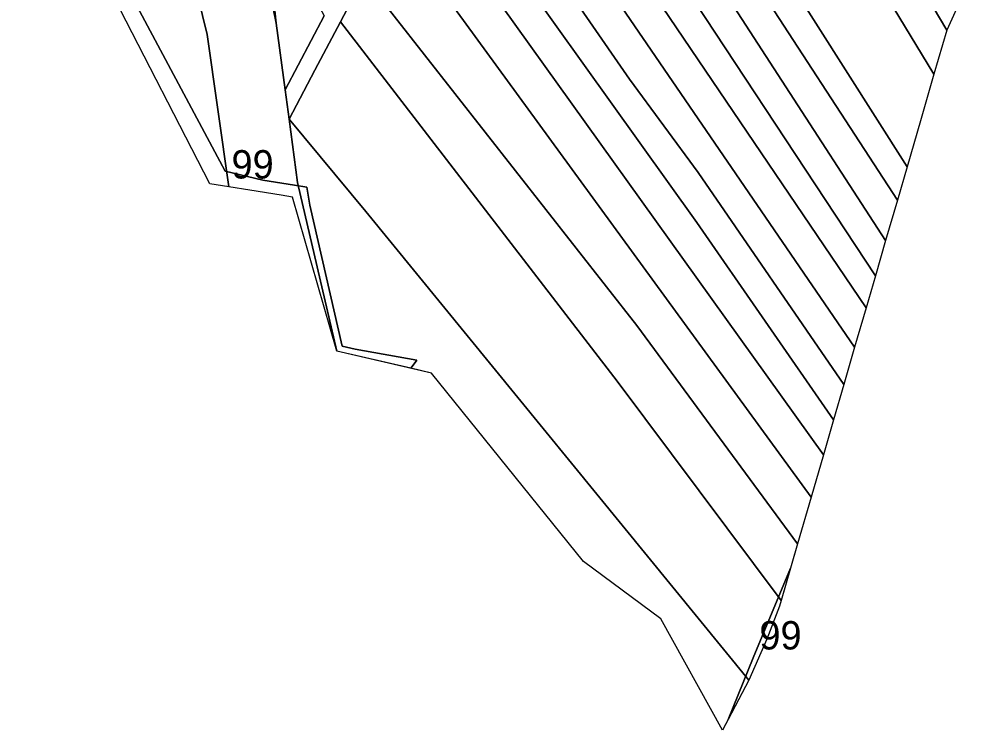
# Model space of a CAD drawing. Extents: x -535894 to -532834, y -1165802 to -1163645.
# Drawn here: x -534290.4 to -534123.9, y -1165556.9 to -1165431.5 of the extents above; entities that cross this region are included whole.
import ezdxf

# ---------------------------------------------------------------- set-up
doc = ezdxf.new("R2010")
doc.units = 0
for name, color, linetype in [('95610013', 7, 'Continuous'), ('95640013', 7, 'Continuous'), ('95660013', 7, 'Continuous')]:
    doc.layers.add(name, color=color, linetype=linetype)

msp = doc.modelspace()

# ---------------------------------------------------------------- linework, layer by layer
at = {"layer": '95610013'}
for points in [[(-534171.44, -1165359.48), (-534166.84, -1165354.83), (-534148.33, -1165384.9), (-534123.86, -1165427.13), (-534126.75, -1165433.55), (-534152.03, -1165390.89)], [(-534176.44, -1165364.53), (-534171.44, -1165359.48), (-534152.03, -1165390.89), (-534126.75, -1165433.55), (-534129.01, -1165441.31), (-534156.72, -1165395.63)], [(-534181.53, -1165369.66), (-534176.44, -1165364.53), (-534156.72, -1165395.63), (-534129.01, -1165441.31), (-534131.39, -1165449.51), (-534133.74, -1165457.61), (-534186.43, -1165374.61)], [(-534190.57, -1165378.79), (-534186.43, -1165374.61), (-534133.74, -1165457.61), (-534135.45, -1165463.49)], [(-534194.5, -1165382.75), (-534190.57, -1165378.79), (-534135.45, -1165463.49), (-534137.53, -1165470.62)], [(-534198.92, -1165387.21), (-534194.5, -1165382.75), (-534137.53, -1165470.62), (-534139.34, -1165476.85), (-534179.96, -1165415.17)], [(-534202.8, -1165391.13), (-534198.92, -1165387.21), (-534179.96, -1165415.17), (-534139.34, -1165476.85), (-534140.98, -1165482.5)], [(-534207.22, -1165395.6), (-534202.8, -1165391.13), (-534140.98, -1165482.5), (-534142.99, -1165489.42)], [(-534211.75, -1165400.17), (-534207.22, -1165395.6), (-534142.99, -1165489.42), (-534144.9, -1165495.99), (-534170.58, -1165458.63), (-534182.69, -1165442.19)], [(-534215.9, -1165404.37), (-534211.75, -1165400.17), (-534182.69, -1165442.19), (-534170.58, -1165458.63), (-534144.9, -1165495.99), (-534146.71, -1165502.23), (-534170.82, -1165467.44)], [(-534220.02, -1165408.52), (-534215.9, -1165404.37), (-534170.82, -1165467.44), (-534146.71, -1165502.23), (-534148.5, -1165508.42)], [(-534224.52, -1165414.59), (-534220.02, -1165408.52), (-534148.5, -1165508.42), (-534150.66, -1165515.85)], [(-534229.56, -1165424.19), (-534224.52, -1165414.59), (-534150.66, -1165515.85), (-534153.04, -1165524.07), (-534181.38, -1165485.61)], [(-534233.69, -1165432.05), (-534229.56, -1165424.19), (-534181.38, -1165485.61), (-534153.04, -1165524.07), (-534155.94, -1165534.08), (-534184.87, -1165495.38)], [(-534238.17, -1165440.59), (-534233.69, -1165432.05), (-534184.87, -1165495.38), (-534155.94, -1165534.08), (-534156.24, -1165535.07), (-534158.49, -1165540.9), (-534161.64, -1165548.15), (-534229.2, -1165465.51), (-534242.7, -1165449.22)], [(-534242.7, -1165449.22), (-534229.2, -1165465.51), (-534161.64, -1165548.15), (-534166.28, -1165556.93), (-534177.14, -1165537.32), (-534190.83, -1165527.2), (-534217.59, -1165493.98), (-534234.3, -1165490.14), (-534241.22, -1165460.36)]]:
    msp.add_lwpolyline(points, close=True, dxfattribs=at)
at = {"layer": '95640013'}
for points in [[(-534259.48, -1165355.88), (-534252.01, -1165352.47), (-534252.23, -1165361.54), (-534251.99, -1165363.99), (-534250.69, -1165377.47), (-534248.48, -1165400.41), (-534247.31, -1165411.07), (-534244.98, -1165432.27), (-534249.38, -1165410.91), (-534252.04, -1165394.43), (-534257.28, -1165359.81), (-534259.04, -1165360.05)], [(-534260.34, -1165356.27), (-534259.48, -1165355.88), (-534259.04, -1165360.05), (-534257.28, -1165359.81), (-534252.04, -1165394.43), (-534249.38, -1165410.91), (-534244.98, -1165432.27), (-534243.4, -1165444.03), (-534242.7, -1165449.22), (-534241.22, -1165460.36), (-534234.3, -1165490.14), (-534242.12, -1165462.96), (-534244.14, -1165462.64), (-534249.66, -1165461.74), (-534253.34, -1165461.15), (-534257.19, -1165434.29), (-534262.04, -1165414.36), (-534266.94, -1165383.2), (-534267.32, -1165359.47), (-534265.74, -1165358.75), (-534264.71, -1165358.28)], [(-534272.9, -1165362.02), (-534265.72, -1165399.2), (-534264.94, -1165402.42), (-534262.04, -1165414.36), (-534257.19, -1165434.29), (-534253.34, -1165461.15), (-534256.73, -1165460.61), (-534273.58, -1165427.79), (-534260.88, -1165425.85), (-534278.69, -1165391.9), (-534290.38, -1165367.27), (-534285.88, -1165365.91), (-534282.54, -1165366.1), (-534281.74, -1165364.67)], [(-534247.31, -1165411.07), (-534236.52, -1165431.02), (-534243.4, -1165444.03), (-534244.98, -1165432.27)]]:
    msp.add_lwpolyline(points, close=True, dxfattribs=at)
msp.add_lwpolyline([(-534229.56, -1165424.19), (-534233.69, -1165432.05), (-534238.17, -1165440.59), (-534242.7, -1165449.22), (-534243.4, -1165444.03), (-534236.52, -1165431.02)], dxfattribs=at)
at = {"layer": '95660013'}
for points in [[(-534221.041, -1165492.816), (-534221.281, -1165493.132), (-534234.3, -1165490.14), (-534242.12, -1165462.96), (-534244.14, -1165462.64), (-534249.66, -1165461.74), (-534253.34, -1165461.15), (-534256.73, -1165460.61), (-534273.58, -1165427.79), (-534263.286, -1165426.218), (-534270, -1165428.46), (-534254.02, -1165458.36), (-534247.37, -1165459.96), (-534241.8, -1165460.84), (-534239.62, -1165461.22), (-534239.05, -1165464.37), (-534233.37, -1165489.25), (-534231.05, -1165489.74), (-534220.2, -1165491.71)], [(-534161.64, -1165548.15), (-534165.283, -1165555.043), (-534160.89, -1165544.2), (-534154.285, -1165528.367), (-534155.94, -1165534.08), (-534156.24, -1165535.07), (-534158.49, -1165540.9)]]:
    msp.add_lwpolyline(points, close=True, dxfattribs=at)
msp.add_lwpolyline([(-534123.86, -1165427.13), (-534126.75, -1165433.55), (-534129.01, -1165441.31), (-534131.39, -1165449.51), (-534133.74, -1165457.61), (-534135.45, -1165463.49), (-534137.53, -1165470.62), (-534139.34, -1165476.85), (-534140.98, -1165482.5), (-534142.99, -1165489.42), (-534144.9, -1165495.99), (-534146.71, -1165502.23), (-534148.5, -1165508.42), (-534150.66, -1165515.85), (-534153.04, -1165524.07), (-534154.285, -1165528.367), (-534160.89, -1165544.2), (-534165.283, -1165555.043), (-534166.28, -1165556.93), (-534177.14, -1165537.32), (-534190.83, -1165527.2), (-534217.59, -1165493.98), (-534221.281, -1165493.132), (-534221.041, -1165492.816), (-534220.2, -1165491.71), (-534231.05, -1165489.74), (-534233.37, -1165489.25), (-534239.05, -1165464.37), (-534239.62, -1165461.22), (-534241.8, -1165460.84), (-534247.37, -1165459.96), (-534254.02, -1165458.36), (-534270, -1165428.46)], dxfattribs=at)

# ---------------------------------------------------------------- texts
for rotation, p in [(360, (-534252.882, -1165459.675)), (0, (-534159.784, -1165542.714))]:
    msp.add_text('99', height=5, rotation=rotation, dxfattribs=at).set_placement(p)

doc.saveas('drawing.dxf')
